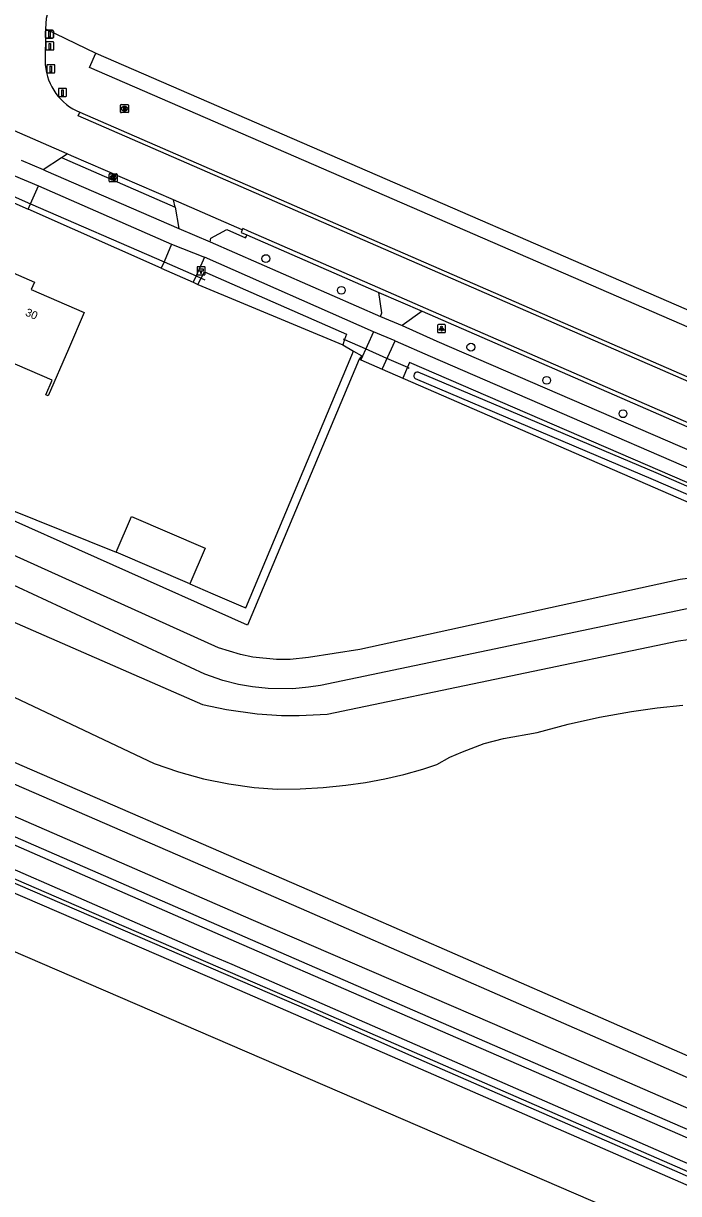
# Model space of a CAD drawing. Extents: x 152881 to 155736, y 382924 to 386919.
# Drawn here: x 153610.1 to 153692, y 385444.8 to 385591.1 of the extents above; entities that cross this region are included whole.
import ezdxf

# ---------------------------------------------------------------- set-up
doc = ezdxf.new("R2010")
doc.units = 0
for name, color, linetype in [('IMGEO_Berm_groen', 7, 'Continuous'), ('IMGEO_Boom', 7, 'Continuous'), ('IMGEO_Brandkraan', 7, 'Continuous'), ('IMGEO_Duiker', 7, 'Continuous'), ('IMGEO_Fietspad_gesloten', 7, 'Continuous'), ('IMGEO_Greppel_droge_sloot', 7, 'Continuous'), ('IMGEO_Groenvoorziening', 7, 'Continuous'), ('IMGEO_Hectometerpaal', 7, 'Continuous'), ('IMGEO_Hek', 7, 'Continuous'), ('IMGEO_Kolk', 7, 'Continuous'), ('IMGEO_Lichtpunt', 7, 'Continuous'), ('IMGEO_Naaldbos', 7, 'Continuous'), ('IMGEO_Paal', 7, 'Continuous'), ('IMGEO_Pand', 7, 'Continuous'), ('IMGEO_Pand_nummerreeks', 7, 'Continuous'), ('IMGEO_Rijbaan_lokaal_gesloten', 7, 'Continuous'), ('IMGEO_Rijbaan_lokaal_halfverhard', 7, 'Continuous'), ('IMGEO_Rijbaan_lokaal_open', 7, 'Continuous'), ('IMGEO_Terreindeel_open', 7, 'Continuous'), ('IMGEO_Verkeersbordpaal', 7, 'Continuous'), ('IMGEO_Waterloop', 7, 'Continuous')]:
    doc.layers.add(name, color=color, linetype=linetype)

msp = doc.modelspace()

# ---------------------------------------------------------------- linework, layer by layer
at = {"layer": 'IMGEO_Berm_groen'}
for points in [[(153822.85, 385477.62), (153771.07, 385500), (153710.9, 385526), (153658.36, 385548.71), (153658.11, 385548.11), (153657.54, 385546.75)], [(153654.97, 385547.87), (153657.54, 385546.75)]]:
    msp.add_lwpolyline(points, dxfattribs=at)
at = {"layer": 'IMGEO_Boom'}
for centre in [(153640.43, 385561.69), (153649.86, 385557.73), (153666.05, 385550.62), (153675.51, 385546.47), (153685.06, 385542.3)]:
    msp.add_circle(centre, 0.489, dxfattribs=at)
at = {"layer": 'IMGEO_Brandkraan'}
for p, q in [((153622.26, 385580), (153622.26, 385580.85)), ((153622.33, 385580.93), (153623.18, 385580.93)), ((153622.74, 385580.71), (153622.77, 385580.71)), ((153623.26, 385580.85), (153623.26, 385580)), ((153623.18, 385579.93), (153622.33, 385579.93)), ((153622.77, 385580.15), (153622.74, 385580.15))]:
    msp.add_line(p, q, dxfattribs=at)
for points in [[(153622.26, 385580), (153622.26, 385580.85)], [(153622.33, 385580.93), (153623.18, 385580.93)], [(153622.6, 385580.63), (153622.6, 385580.23), (153622.82, 385580.23)], [(153622.83, 385580.63), (153622.6, 385580.63)], [(153622.78, 385580.55), (153622.73, 385580.55), (153622.73, 385580.47)], [(153622.73, 385580.47), (153622.78, 385580.47)], [(153622.79, 385580.39), (153622.73, 385580.39), (153622.73, 385580.31)], [(153623.26, 385580.85), (153623.26, 385580)], [(153623.18, 385579.93), (153622.33, 385579.93)], [(153622.73, 385580.31), (153622.79, 385580.31)]]:
    msp.add_lwpolyline(points, dxfattribs=at)
for centre, radius, start, end in [((153622.33, 385580.85), 0.0765, 91.552, 178.448), ((153622.33, 385580.85), 0.0765, 91.552, 178.448), ((153622.78, 385580.51), 0.0379, 267.8285, 90.9355), ((153622.79, 385580.35), 0.0404, 269.8759, 90.5077), ((153622.84, 385580.48), 0.145, 59.4692, 91.5367), ((153622.86, 385580.53), 0.0922, 285.5137, 58.1501), ((153622.87, 385580.34), 0.105, 301.3115, 78.989), ((153623.18, 385580.85), 0.0765, 1.552, 88.448), ((153623.18, 385580.85), 0.0765, 1.552, 88.448), ((153622.33, 385580), 0.0765, 181.552, 268.448), ((153622.33, 385580), 0.0765, 181.552, 268.448), ((153622.82, 385580.48), 0.251, 268.6676, 293.5347), ((153623.18, 385580), 0.0765, 271.552, 358.448), ((153623.18, 385580), 0.0765, 271.552, 358.448)]:
    msp.add_arc(centre, radius, start, end, dxfattribs=at)
for centre, major_axis, ratio, start_param, end_param in [((153622.74, 385580.43), (-0.387, 0.002), 0.722429, 4.712389, 7.853982), ((153622.77, 385580.43), (-0.39, 0.002), 0.717154, 1.570796, 4.712389)]:
    msp.add_ellipse(centre, major_axis=major_axis, ratio=ratio, start_param=start_param, end_param=end_param, dxfattribs=at)
at = {"layer": 'IMGEO_Duiker'}
for points in [[(153602.38, 385572.31), (153608.08, 385569.83), (153611.02, 385568.54), (153627.7, 385561.27), (153631.7, 385559.52), (153632.34, 385559.24), (153632.8, 385559.04)], [(153650.1, 385551.65), (153650.27, 385551.58), (153652.84, 385550.44), (153655.52, 385549.26), (153658.11, 385548.11), (153658.35, 385548)]]:
    msp.add_lwpolyline(points, dxfattribs=at)
at = {"layer": 'IMGEO_Fietspad_gesloten'}
for points in [[(153612.61, 385572.82), (153612.95, 385572.67), (153629.55, 385565.43)], [(153612, 385570.77), (153628.63, 385563.5)], [(153633.48, 385563.79), (153654.74, 385554.44)], [(153653.88, 385552.55), (153632.74, 385561.85)], [(153657.44, 385553.33), (153661.81, 385551.39), (153712.41, 385529.52), (153723.97, 385524.52), (153755.94, 385510.49), (153779.92, 385500), (153822.12, 385481.53)], [(153656.58, 385551.42), (153660.96, 385549.48), (153711.57, 385527.57), (153722.99, 385522.62), (153755.1, 385508.53), (153774.58, 385500), (153821.11, 385479.62)]]:
    msp.add_lwpolyline(points, dxfattribs=at)
at = {"layer": 'IMGEO_Greppel_droge_sloot'}
for points in [[(153631.94, 385558.47), (153632.34, 385559.24), (153632.74, 385560.04), (153650.52, 385552.26), (153650.27, 385551.58), (153650.03, 385550.93)], [(153631.94, 385558.47), (153650.03, 385550.93)]]:
    msp.add_lwpolyline(points, dxfattribs=at)
at = {"layer": 'IMGEO_Groenvoorziening'}
for points in [[(153753.96, 385432.78), (153718.2, 385448.32), (153682.6, 385463.95), (153644.87, 385480.42), (153603.55, 385498.34), (153565.17, 385515.08), (153526.53, 385531.86), (153485.4, 385549.72), (153447.11, 385566.37), (153404.43, 385584.91), (153391.13, 385553.82), (153377.7, 385522.52), (153363.12, 385488.48), (153361.93, 385485.7), (153349.03, 385455.59), (153333.68, 385419.73)], [(153652.09, 385549.13), (153638.14, 385515.87), (153587.72, 385538.37), (153601.33, 385571.22)], [(153749.15, 385424.11), (153636.23, 385473.49), (153633.05, 385474.8), (153590.73, 385493.3), (153497.75, 385533.39), (153416.79, 385568.69), (153415.61, 385569.07), (153414.39, 385569.29), (153413.16, 385569.37), (153411.92, 385569.32), (153410.03, 385568.99), (153409.13, 385568.66), (153408.3, 385568.17), (153407.63, 385567.58), (153407.06, 385566.88), (153406.61, 385566.11), (153401.78, 385555.15), (153379.55, 385503.43), (153360.1, 385457.74), (153350.86, 385436.41)], [(153627.36, 385560.49), (153610.71, 385567.88)], [(153631.34, 385558.73), (153631.94, 385558.47)], [(153906.33, 385461.14), (153889.11, 385452.93), (153851.3, 385434.86), (153815.69, 385417.92), (153793.05, 385418.58), (153754.96, 385435.07), (153719.2, 385450.61), (153683.61, 385466.24), (153645.87, 385482.71), (153604.55, 385500.64), (153566.16, 385517.37), (153527.53, 385534.15), (153486.39, 385552.01), (153472.44, 385558.07)], [(153650.03, 385550.93), (153651.39, 385550.13)], [(153651.39, 385550.13), (153652.4, 385549.54), (153652.09, 385549.13)], [(153652.09, 385549.13), (153652.28, 385549.04)], [(153657.54, 385546.75), (153822, 385475.26), (153824.96, 385474.08), (153828.05, 385472.99), (153834.3, 385471.24), (153840.67, 385470.04), (153847.12, 385469.4), (153853.6, 385469.31), (153856.78, 385469.55), (153858.85, 385469.7), (153860.12, 385469.8), (153862.4, 385470.16)], [(153481.76, 385537.54), (153479.04, 385531.15), (153796.71, 385394.08), (153797.85, 385393.82), (153799.57, 385393.42), (153800.87, 385393.29), (153802.52, 385393.11), (153804.24, 385393.14), (153805.44, 385393.16), (153805.86, 385393.2), (153812.14, 385399.11), (153812.15, 385399.33)], [(153481.76, 385537.54), (153496.79, 385530.96), (153542.67, 385511.24), (153589.62, 385490.75), (153634.91, 385471.23), (153658.13, 385461.13), (153748.16, 385421.9), (153793.34, 385402.67), (153798.66, 385400.82), (153800.73, 385400.34), (153802.84, 385400.12), (153805.04, 385400.15), (153805.18, 385400.16)], [(153823.43, 385470.59), (153752.72, 385501.78), (153707.63, 385520.73), (153704.68, 385521.48), (153701.42, 385521.98), (153699.55, 385522.12), (153697.46, 385522.14), (153695.24, 385522.01), (153692.2, 385521.59), (153652.15, 385512.84), (153645.76, 385511.83), (153643.47, 385511.6), (153641.75, 385511.59), (153638.8, 385511.88), (153637.24, 385512.2), (153634.51, 385513.05), (153586.27, 385534.82)], [(153577.89, 385521.59), (153626.46, 385498.61), (153629.5, 385497.54), (153632.62, 385496.68), (153635.78, 385496.04), (153638.98, 385495.6), (153641.84, 385495.4), (153644.71, 385495.41), (153647.57, 385495.59), (153650.42, 385495.87), (153652.86, 385496.21), (153655.28, 385496.67), (153657.68, 385497.23), (153660.05, 385497.9), (153661.79, 385498.46), (153663.43, 385499.38), (153665, 385500.04), (153667.7, 385501.09), (153670.13, 385501.7), (153674.33, 385502.48), (153678.19, 385503.51), (153682.13, 385504.38), (153686.1, 385505.09), (153689.31, 385505.54), (153692.54, 385505.9)], [(153749.92, 385426.95), (153704.47, 385446.85), (153667.33, 385462.98), (153637.41, 385475.99), (153591.92, 385495.82)]]:
    msp.add_lwpolyline(points, dxfattribs=at)
at = {"layer": 'IMGEO_Hectometerpaal'}
for p, q in [((153631.84, 385560.59), (153631.84, 385559.75)), ((153631.84, 385560.59), (153631.84, 385559.75)), ((153632.75, 385560.68), (153631.91, 385560.68)), ((153632.75, 385560.68), (153631.91, 385560.68)), ((153632.84, 385559.76), (153632.84, 385560.6)), ((153632.84, 385559.76), (153632.84, 385560.6)), ((153631.92, 385559.68), (153632.76, 385559.68)), ((153631.92, 385559.68), (153632.76, 385559.68))]:
    msp.add_line(p, q, dxfattribs=at)
msp.add_lwpolyline([(153632.36, 385559.82), (153632.3, 385559.82), (153632.3, 385560.12), (153632.08, 385560.12), (153632.08, 385560.39), (153632.58, 385560.39), (153632.58, 385560.12), (153632.36, 385560.12), (153632.36, 385559.82)], dxfattribs=at)
for centre, start, end in [((153631.92, 385560.6), 92.4484, 184.2845), ((153631.92, 385560.6), 92.4484, 184.2845), ((153632.76, 385560.6), 2.4484, 94.2845), ((153632.76, 385560.6), 2.4484, 94.2845), ((153631.92, 385559.75), 182.4484, 274.2845), ((153631.92, 385559.75), 182.4484, 274.2845), ((153632.76, 385559.75), 272.4484, 4.2845), ((153632.76, 385559.75), 272.4484, 4.2845)]:
    msp.add_arc(centre, 0.0779, start, end, dxfattribs=at)
at = {"layer": 'IMGEO_Hek'}
for points in [[(153753.96, 385432.78), (153718.2, 385448.32), (153682.6, 385463.95), (153644.87, 385480.42), (153603.55, 385498.34), (153565.17, 385515.08), (153526.53, 385531.86), (153485.4, 385549.72), (153469.6, 385556.59), (153447.11, 385566.37), (153404.43, 385584.91), (153391.13, 385553.82), (153377.7, 385522.52), (153363.12, 385488.48), (153361.93, 385485.7), (153349.03, 385455.59), (153333.68, 385419.73)], [(153633.81, 385519.81), (153637.58, 385518.18), (153637.92, 385518.03), (153651.17, 385549.6)], [(153630.93, 385521.05), (153633.81, 385519.81)]]:
    msp.add_lwpolyline(points, dxfattribs=at)
at = {"layer": 'IMGEO_Kolk'}
for p, q in [((153620.84, 385571.36), (153620.84, 385572.21)), ((153620.92, 385572.29), (153621.77, 385572.29)), ((153621.33, 385572.07), (153621.35, 385572.07)), ((153621.84, 385572.21), (153621.84, 385571.36)), ((153621.77, 385571.29), (153620.92, 385571.29)), ((153621.35, 385571.51), (153621.33, 385571.51))]:
    msp.add_line(p, q, dxfattribs=at)
for points in [[(153620.84, 385571.36), (153620.84, 385572.21)], [(153620.92, 385572.29), (153621.77, 385572.29)], [(153621.16, 385571.99), (153621.29, 385571.99), (153621.29, 385571.84), (153621.41, 385571.99), (153621.58, 385571.99), (153621.43, 385571.84), (153621.59, 385571.59), (153621.43, 385571.59), (153621.35, 385571.75), (153621.29, 385571.69), (153621.29, 385571.59), (153621.16, 385571.59), (153621.16, 385571.99)], [(153621.84, 385572.21), (153621.84, 385571.36)], [(153621.77, 385571.29), (153620.92, 385571.29)]]:
    msp.add_lwpolyline(points, dxfattribs=at)
for centre, start, end in [((153620.92, 385572.21), 91.552, 178.448), ((153620.92, 385572.21), 91.552, 178.448), ((153621.77, 385572.21), 1.552, 88.448), ((153621.77, 385572.21), 1.552, 88.448), ((153620.92, 385571.36), 181.552, 268.448), ((153620.92, 385571.36), 181.552, 268.448), ((153621.77, 385571.36), 271.552, 358.448), ((153621.77, 385571.36), 271.552, 358.448)]:
    msp.add_arc(centre, 0.0765, start, end, dxfattribs=at)
for centre, major_axis, ratio, start_param, end_param in [((153621.33, 385571.79), (-0.387, 0.002), 0.722429, 4.712389, 7.853982), ((153621.35, 385571.79), (-0.39, 0.002), 0.717154, 1.570796, 4.712389)]:
    msp.add_ellipse(centre, major_axis=major_axis, ratio=ratio, start_param=start_param, end_param=end_param, dxfattribs=at)
at = {"layer": 'IMGEO_Lichtpunt'}
for p, q in [((153661.88, 385553.34), (153661.88, 385552.53)), ((153661.88, 385553.34), (153661.88, 385552.53)), ((153662.78, 385553.44), (153661.98, 385553.44)), ((153662.78, 385553.44), (153661.98, 385553.44)), ((153662.88, 385552.53), (153662.88, 385553.34)), ((153662.88, 385552.53), (153662.88, 385553.34)), ((153661.98, 385552.44), (153662.78, 385552.44)), ((153661.98, 385552.44), (153662.78, 385552.44))]:
    msp.add_line(p, q, dxfattribs=at)
for points in [[(153662.26, 385553), (153662.3, 385552.98), (153662.11, 385552.71), (153662.07, 385552.74), (153662.26, 385553)], [(153662.36, 385552.96), (153662.41, 385552.96), (153662.41, 385552.63), (153662.36, 385552.63), (153662.36, 385552.96)], [(153662.47, 385552.98), (153662.51, 385553), (153662.69, 385552.74), (153662.66, 385552.71), (153662.47, 385552.98)]]:
    msp.add_lwpolyline(points, dxfattribs=at)
msp.add_circle((153662.38, 385553.14), 0.0994, dxfattribs=at)
for centre, start, end in [((153661.98, 385553.34), 90, 180), ((153661.98, 385553.34), 90, 180), ((153662.78, 385553.34), 0, 90), ((153662.78, 385553.34), 0, 90), ((153661.98, 385552.53), 180, 270), ((153661.98, 385552.53), 180, 270), ((153662.78, 385552.53), 270, 0), ((153662.78, 385552.53), 270, 360)]:
    msp.add_arc(centre, 0.0946, start, end, dxfattribs=at)
at = {"layer": 'IMGEO_Naaldbos'}
msp.add_lwpolyline([(153612.9, 385590.39), (153619.18, 385587.36)], dxfattribs=at)
at = {"layer": 'IMGEO_Paal'}
for p, q in [((153612.95, 385588.67), (153612.95, 385587.83)), ((153612.95, 385588.67), (153612.95, 385587.83)), ((153613.86, 385588.76), (153613.02, 385588.76)), ((153613.86, 385588.76), (153613.02, 385588.76)), ((153613.03, 385587.76), (153613.87, 385587.76)), ((153613.03, 385587.76), (153613.87, 385587.76)), ((153613.95, 385587.84), (153613.95, 385588.68)), ((153613.95, 385587.84), (153613.95, 385588.68)), ((153613.07, 385585.84), (153613.07, 385585)), ((153613.07, 385585.84), (153613.07, 385585)), ((153613.99, 385585.92), (153613.15, 385585.92)), ((153613.99, 385585.92), (153613.15, 385585.92)), ((153613.16, 385584.92), (153614, 385584.92)), ((153613.16, 385584.92), (153614, 385584.92)), ((153614.07, 385585.01), (153614.07, 385585.85)), ((153614.07, 385585.01), (153614.07, 385585.85)), ((153614.52, 385582.88), (153614.52, 385582.04)), ((153614.52, 385582.88), (153614.52, 385582.04)), ((153615.43, 385582.96), (153614.59, 385582.96)), ((153615.43, 385582.96), (153614.59, 385582.96)), ((153614.6, 385581.96), (153615.44, 385581.96)), ((153614.6, 385581.96), (153615.44, 385581.96)), ((153615.52, 385582.05), (153615.52, 385582.89)), ((153615.52, 385582.05), (153615.52, 385582.89))]:
    msp.add_line(p, q, dxfattribs=at)
for points in [[(153613.36, 385588.57), (153613.52, 385588.57), (153613.52, 385587.84), (153613.36, 385587.84), (153613.36, 385588.57)], [(153613.49, 385585.73), (153613.65, 385585.73), (153613.65, 385585), (153613.49, 385585), (153613.49, 385585.73)], [(153614.93, 385582.77), (153615.09, 385582.77), (153615.09, 385582.04), (153614.93, 385582.04), (153614.93, 385582.77)]]:
    msp.add_lwpolyline(points, dxfattribs=at)
for centre, start, end in [((153613.02, 385588.68), 92.4484, 184.2845), ((153613.02, 385588.68), 92.4484, 184.2845), ((153613.02, 385587.83), 182.4484, 274.2845), ((153613.02, 385587.83), 182.4484, 274.2845), ((153613.87, 385588.68), 2.4484, 94.2845), ((153613.87, 385588.68), 2.4484, 94.2845), ((153613.87, 385587.83), 272.4484, 4.2845), ((153613.87, 385587.83), 272.4484, 4.2845), ((153613.15, 385585.84), 92.4484, 184.2845), ((153613.15, 385585.84), 92.4484, 184.2845), ((153613.15, 385585), 182.4484, 274.2845), ((153613.15, 385585), 182.4484, 274.2845), ((153613.99, 385585.84), 2.4484, 94.2845), ((153613.99, 385585.84), 2.4484, 94.2845), ((153613.99, 385585), 272.4484, 4.2845), ((153613.99, 385585), 272.4484, 4.2845), ((153614.59, 385582.88), 92.4484, 184.2845), ((153614.59, 385582.88), 92.4484, 184.2845), ((153614.59, 385582.04), 182.4484, 274.2845), ((153614.59, 385582.04), 182.4484, 274.2845), ((153615.44, 385582.88), 2.4484, 94.2845), ((153615.44, 385582.88), 2.4484, 94.2845), ((153615.44, 385582.04), 272.4484, 4.2845), ((153615.44, 385582.04), 272.4484, 4.2845)]:
    msp.add_arc(centre, 0.0779, start, end, dxfattribs=at)
at = {"layer": 'IMGEO_Pand'}
for points in [[(153613.24, 385544.54), (153612.94, 385544.67), (153613.73, 385546.51), (153603.49, 385550.92), (153602.7, 385549.08), (153596.52, 385551.75), (153597.36, 385553.71), (153599.42, 385558.27), (153605.23, 385555.72), (153607.33, 385560.56), (153607.52, 385560.48), (153611.52, 385558.75), (153611.11, 385557.83), (153617.74, 385554.96), (153615.76, 385550.37), (153613.24, 385544.54)], [(153621.73, 385525.02), (153623.64, 385529.46), (153632.85, 385525.49), (153630.93, 385521.05)], [(153630.93, 385521.05), (153621.73, 385525.02)]]:
    msp.add_lwpolyline(points, dxfattribs=at)
at = {"layer": 'IMGEO_Rijbaan_lokaal_gesloten'}
for points in [[(153615.64, 385601.61), (153612.97, 385591.68), (153612.9, 385590.39)], [(153612.9, 385590.39), (153612.85, 385585.91)], [(153821.61, 385490.38), (153616.99, 385579.54), (153617.19, 385579.99)], [(153617.19, 385579.99), (153821.78, 385490.87)], [(153615.59, 385574.79), (153609.03, 385577.65)], [(153614.88, 385574.32), (153615.59, 385574.79)], [(153628.89, 385569.02), (153616.15, 385574.55), (153615.59, 385574.79)], [(153614.88, 385574.32), (153615.27, 385574.15), (153629.08, 385568.13)], [(153629.08, 385568.13), (153628.89, 385569.02)], [(153637.47, 385565.29), (153628.89, 385569.02)], [(153637.47, 385565.29), (153637.33, 385564.97), (153638.06, 385564.65)], [(153821.98, 385485.03), (153660.42, 385555.46), (153654.42, 385558.08), (153638.26, 385565.12), (153637.53, 385565.43), (153637.47, 385565.29)], [(153638.06, 385564.65), (153654.53, 385557.47)], [(153654.53, 385557.47), (153659.95, 385555.11)], [(153659.95, 385555.11), (153821.79, 385484.58)]]:
    msp.add_lwpolyline(points, dxfattribs=at)
msp.add_arc((153619.8, 385586.44), 6.96, 184.3937, 247.9906, dxfattribs=at)
at = {"layer": 'IMGEO_Rijbaan_lokaal_halfverhard'}
for points in [[(153751.15, 385430.11), (153705.64, 385450.04), (153668.73, 385466.1), (153638.59, 385479.09), (153593.32, 385498.81)], [(153592.32, 385496.73), (153637.81, 385476.91), (153667.73, 385463.9), (153704.87, 385447.77), (153750.32, 385427.87)]]:
    msp.add_lwpolyline(points, dxfattribs=at)
at = {"layer": 'IMGEO_Rijbaan_lokaal_open'}
for points in [[(153609.87, 385573.99), (153612.61, 385572.82)], [(153612.61, 385572.82), (153614.88, 385574.32)], [(153608.95, 385572.08), (153612, 385570.77)], [(153610.71, 385567.88), (153611.02, 385568.54), (153612, 385570.77)], [(153607.8, 385569.17), (153610.71, 385567.88)], [(153629.08, 385568.13), (153629.55, 385565.43)], [(153629.55, 385565.43), (153633.48, 385563.79)], [(153633.48, 385563.79), (153633.57, 385564.26), (153635.53, 385565.31), (153637.9, 385564.28), (153638, 385564.51), (153638.06, 385564.65)], [(153628.63, 385563.5), (153627.7, 385561.27), (153627.36, 385560.49)], [(153628.63, 385563.5), (153632.74, 385561.85)], [(153632.74, 385561.85), (153631.7, 385559.52), (153631.34, 385558.73)], [(153627.36, 385560.49), (153631.34, 385558.73)], [(153654.74, 385554.44), (153654.94, 385554.93), (153654.53, 385557.47)], [(153654.74, 385554.44), (153657.44, 385553.33)], [(153659.95, 385555.11), (153657.44, 385553.33)], [(153653.88, 385552.55), (153652.28, 385549.04)], [(153656.58, 385551.42), (153653.88, 385552.55)], [(153654.97, 385547.87), (153656.58, 385551.42)], [(153652.28, 385549.04), (153654.97, 385547.87)]]:
    msp.add_lwpolyline(points, dxfattribs=at)
at = {"layer": 'IMGEO_Terreindeel_open'}
for points in [[(153602.59, 385571.47), (153589.06, 385538.99), (153608.27, 385530.42), (153621.73, 385525.02)], [(153630.93, 385521.05), (153633.81, 385519.81), (153637.58, 385518.18), (153637.92, 385518.03), (153651.17, 385549.6), (153651.39, 385550.13)]]:
    msp.add_lwpolyline(points, dxfattribs=at)
at = {"layer": 'IMGEO_Verkeersbordpaal'}
for p, q in [((153612.89, 385589.33), (153612.89, 385590.13)), ((153612.89, 385590.13), (153612.89, 385589.33)), ((153612.99, 385590.23), (153613.78, 385590.23)), ((153613.78, 385590.23), (153612.99, 385590.23)), ((153613.78, 385589.23), (153612.99, 385589.23)), ((153612.99, 385589.23), (153613.78, 385589.23)), ((153613.88, 385590.13), (153613.88, 385589.33)), ((153613.88, 385589.33), (153613.88, 385590.13))]:
    msp.add_line(p, q, dxfattribs=at)
msp.add_lwpolyline([(153613.31, 385590.11), (153613.46, 385590.11), (153613.46, 385589.36), (153613.31, 385589.36), (153613.31, 385590.11)], dxfattribs=at)
for centre, start, end in [((153612.99, 385590.13), 90, 180), ((153612.99, 385590.13), 90, 180), ((153612.99, 385589.33), 180, 270), ((153612.99, 385589.33), 180, 270), ((153613.78, 385590.13), 0, 90), ((153613.78, 385590.13), 360, 90), ((153613.78, 385589.33), 270, 0), ((153613.78, 385589.33), 270, 0)]:
    msp.add_arc(centre, 0.1, start, end, dxfattribs=at)
at = {"layer": 'IMGEO_Waterloop'}
for points in [[(153823.06, 385496.79), (153815.66, 385500), (153717.94, 385542.39), (153618.4, 385585.57), (153619.18, 385587.36)], [(153619.18, 385587.36), (153718.71, 385544.19), (153820.58, 385500), (153823.9, 385498.56)], [(153351.75, 385436.01), (153402.05, 385553.39), (153407.65, 385565.78), (153408.2, 385566.53), (153408.87, 385567.18), (153409.64, 385567.71), (153410.51, 385568.1), (153411.45, 385568.32), (153413.36, 385568.42), (153414.51, 385568.31), (153415.65, 385568.09), (153416.76, 385567.73), (153463.21, 385547.36), (153621.44, 385478.82), (153644.62, 385468.77), (153725.08, 385433.67), (153784.8, 385407.82), (153796.87, 385402.92), (153799.64, 385402.11), (153801.1, 385401.83), (153803.4, 385401.59), (153805.26, 385401.56)], [(153352.2, 385435.81), (153380.9, 385502.94), (153405.22, 385559.35), (153408.24, 385565.55), (153408.75, 385566.25), (153409.36, 385566.85), (153410.07, 385567.35), (153410.85, 385567.7), (153411.76, 385567.91), (153412.69, 385567.9), (153415.38, 385567.46), (153417.05, 385566.93), (153462.96, 385546.83), (153497.42, 385531.97), (153543.11, 385512.1), (153644.56, 385468.29), (153658.54, 385462.08), (153748.59, 385422.82)], [(153860.02, 385471.29), (153849.18, 385471.16), (153844.1, 385471.29), (153838.2, 385472.23), (153833.71, 385473.23), (153829.1, 385474.47), (153824.14, 385476.16), (153800.99, 385486.03), (153747.38, 385509.51), (153711.8, 385525.09), (153689.18, 385534.91), (153659.44, 385547.5)], [(153659.1, 385546.69), (153688.84, 385534.1), (153711.45, 385524.28), (153747.02, 385508.7), (153800.64, 385485.22), (153823.82, 385475.34), (153828.85, 385473.63), (153833.5, 385472.37), (153838.03, 385471.36), (153844.02, 385470.41), (153849.17, 385470.28), (153860.03, 385470.41)], [(153823.51, 385467.35), (153776.02, 385487.85), (153707.85, 385516.52), (153706.32, 385517.08), (153704.57, 385517.6), (153701.8, 385518.16), (153699.92, 385518.37), (153697.55, 385518.44), (153694.46, 385518.21), (153647.27, 385508.35), (153645.76, 385508.11), (153643.8, 385507.93), (153640.71, 385507.95), (153638.76, 385508.16), (153637.02, 385508.47), (153635.07, 385508.98), (153632.82, 385509.77), (153582.6, 385533.08)], [(153583.85, 385527.22), (153632.5, 385505.98), (153635.49, 385505.33), (153639.32, 385504.79), (153642.39, 385504.59), (153644.59, 385504.57), (153648.1, 385504.75), (153692.01, 385513.94), (153694.4, 385514.27), (153696.26, 385514.4), (153698.03, 385514.43), (153700.15, 385514.33), (153703.45, 385513.91), (153705.69, 385513.43), (153707.7, 385512.85), (153756.29, 385492.76), (153800.76, 385473.73), (153817.03, 385466.67)]]:
    msp.add_lwpolyline(points, dxfattribs=at)
msp.add_arc((153659.38, 385547.05), 0.457, 82.3113, 231.7693, dxfattribs=at)

# ---------------------------------------------------------------- texts
at = {"layer": 'IMGEO_Pand_nummerreeks'}
msp.add_text('30', height=1, rotation=336.6429, dxfattribs=at).set_placement((153610.28, 385554.61))

doc.saveas('drawing.dxf')
